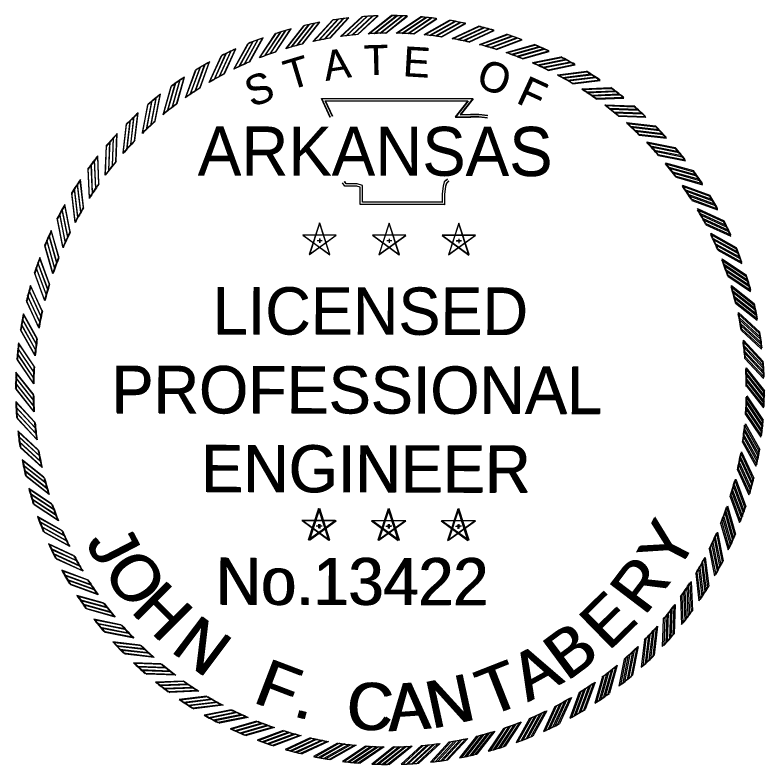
# Model space of a CAD drawing. Extents: x 982240 to 1103002, y 974866 to 1054902.
# Drawn here: x 1095709 to 1103002, y 976312 to 983600 of the extents above; entities that cross this region are included whole.
import ezdxf

# ---------------------------------------------------------------- set-up
doc = ezdxf.new("R2010")
doc.units = 0
doc.layers.add('Default', color=7, linetype='Continuous')

# ---------------------------------------------------------------- blocks, each defined once
blk = doc.blocks.new('STAR')
at = {"layer": 'Default'}
for p, q in [((-0.0001, 0.0615), (-0.0366, -0.0504)), ((0.0362, -0.0503), (0, 0.0617)), ((0.0587, 0.0188), (-0.059, 0.0189)), ((-0.0589, 0.0188), (0.0363, -0.0505)), ((-0.0365, -0.0503), (0.0589, 0.0188)), ((-0.0085, 0), (0.009, 0)), ((0, 0.0063), (0, -0.0085))]:
    blk.add_line(p, q, dxfattribs=at)
blk = doc.blocks.new('RP')
at = {"layer": 'Default'}
for p, q in [((-0.0781, 1.2656), (0.003, 1.33)), ((-0.058, 1.2667), (0.0216, 1.3299)), ((-0.0375, 1.2674), (0.0405, 1.3294)), ((-0.0176, 1.2679), (0.059, 1.3287))]:
    blk.add_line(p, q, dxfattribs=at)
for radius, start, end in [(1.33, 87.4562, 89.8699), (1.268, 90.7933, 93.5307)]:
    blk.add_arc((0, 0), radius, start, end, dxfattribs=at)

msp = doc.modelspace()

# ---------------------------------------------------------------- linework, layer by layer
at = {"layer": 'Default'}
for points in [[(1098774.1, 982603.7), (1098689, 982787.9), (1100160.3, 982788.7), (1100037.4, 982634.3), (1100137.3, 982635.6), (1100220.8, 982636.7), (1100304.2, 982627.6)], [(1098777, 982604.7), (1098692.6, 982789.1), (1100163.8, 982785), (1100040.3, 982630.9), (1100140.3, 982631.9), (1100223.8, 982632.7), (1100307.2, 982623.3)], [(1098795.2, 982613.5), (1098725.5, 982764.6), (1100111.9, 982765.4), (1099988.5, 982610.3), (1100137.6, 982612.3), (1100219.7, 982613.3), (1100301.7, 982604.4)], [(1098798.1, 982614.4), (1098728.9, 982765.7), (1100115.4, 982761.8), (1099991.4, 982607.2), (1100140.5, 982608.6), (1100222.6, 982609.4), (1100304.6, 982600.2)], [(1099928.4, 981987.2), (1099903.3, 981966.8), (1099895, 981936.2), (1099886.7, 981860), (1099886.7, 981758.3), (1099065.4, 981758.3), (1099065.4, 981895.6), (1099065.4, 981926.1), (1099032.1, 981936.2), (1098915.3, 981936.2), (1098894.5, 981967.9)], [(1099929.2, 981984.2), (1099904.1, 981963.9), (1099895.6, 981933.4), (1099887, 981857.2), (1099886.7, 981755.5), (1099065.4, 981758.3), (1099065.9, 981895.6), (1099066, 981926.1), (1099032.7, 981936.4), (1098915.9, 981936.8), (1098895.2, 981968.5)], [(1099913.7, 982005.3), (1099882.8, 981980.1), (1099872.1, 981940.6), (1099863.4, 981861.2), (1099863.4, 981781.6), (1099088.7, 981781.6), (1099088.7, 981895.6), (1099088.7, 981943.3), (1099035.6, 981959.5), (1098927.9, 981959.5), (1098914, 981980.7)], [(1099914.6, 982002.4), (1099883.6, 981977.3), (1099872.7, 981937.8), (1099863.7, 981858.5), (1099863.5, 981778.9), (1099088.8, 981781.5), (1099089.2, 981895.5), (1099089.3, 981943.2), (1099036.3, 981959.6), (1098928.5, 981960), (1098914.8, 981981.2)]]:
    msp.add_lwpolyline(points, dxfattribs=at)

# ---------------------------------------------------------------- block references
for name, p, xscale, yscale, rotation in [('RP', (1099358.4, 979956.4), 2735.2966029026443, 2735.2966029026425, 9.000000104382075), ('RP', (1099352.3, 979955.4), 2735.296602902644, 2735.2966029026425, 8.804199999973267), ('RP', (1099358.4, 979956.4), 2735.2966029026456, 2735.2966029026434, 4.500000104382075), ('RP', (1099352.3, 979955.4), 2735.296602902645, 2735.2966029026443, 4.304199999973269), ('RP', (1099358.4, 979956.4), 2735.2966029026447, 2735.296602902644, 1.0438208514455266e-07), ('RP', (1099352.3, 979955.4), 2735.2966029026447, 2735.296602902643, -0.19580000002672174), ('RP', (1099358.4, 979956.4), 2735.296602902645, 2735.296602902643, -4.499999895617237), ('RP', (1099352.3, 979955.4), 2735.2966029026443, 2735.2966029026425, -4.695800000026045), ('RP', (1099358.4, 979956.4), 2735.296602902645, 2735.2966029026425, -8.999999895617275), ('RP', (1099352.3, 979955.4), 2735.2966029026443, 2735.296602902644, -9.195800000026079), ('RP', (1099358.4, 979956.4), 2735.2966029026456, 2735.2966029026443, -13.499999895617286), ('RP', (1099358.4, 979956.4), 2735.296602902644, 2735.296602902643, 13.500000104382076), ('RP', (1099352.3, 979955.4), 2735.296602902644, 2735.296602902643, 13.304199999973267), ('RP', (1099352.3, 979955.4), 2735.296602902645, 2735.2966029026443, -13.695800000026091), ('RP', (1099358.4, 979956.4), 2735.296602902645, 2735.2966029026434, -17.999999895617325), ('RP', (1099352.3, 979955.4), 2735.296602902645, 2735.296602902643, -18.195800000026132), ('RP', (1099358.4, 979956.4), 2735.2966029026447, 2735.2966029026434, 18.00000010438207), ('RP', (1099352.3, 979955.4), 2735.2966029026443, 2735.2966029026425, 17.80419999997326), ('RP', (1099358.4, 979956.4), 2735.2966029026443, 2735.296602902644, -22.499999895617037), ('RP', (1099358.4, 979956.4), 2735.2966029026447, 2735.2966029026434, 22.50000010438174), ('RP', (1099352.3, 979955.4), 2735.2966029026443, 2735.2966029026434, 22.304199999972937), ('RP', (1099352.3, 979955.4), 2735.2966029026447, 2735.2966029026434, -22.69580000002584), ('RP', (1099358.4, 979956.4), 2735.2966029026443, 2735.2966029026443, 27.000000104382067), ('RP', (1099352.3, 979955.4), 2735.2966029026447, 2735.2966029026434, 26.80419999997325), ('RP', (1099358.4, 979956.4), 2735.2966029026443, 2735.2966029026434, -26.99999989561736), ('RP', (1099352.3, 979955.4), 2735.2966029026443, 2735.296602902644, -27.195800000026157), ('RP', (1099358.4, 979956.4), 2735.296602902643, 2735.2966029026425, 31.50000010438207), ('RP', (1099352.3, 979955.4), 2735.296602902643, 2735.2966029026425, 31.30419999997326), ('RP', (1099358.4, 979956.4), 2735.2966029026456, 2735.2966029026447, -31.499999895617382), ('RP', (1099352.3, 979955.4), 2735.2966029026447, 2735.2966029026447, -31.695800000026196), ('RP', (1099358.4, 979956.4), 2735.296602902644, 2735.296602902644, 36.00000010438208), ('RP', (1099352.3, 979955.4), 2735.2966029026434, 2735.2966029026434, 35.804199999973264), ('RP', (1099358.4, 979956.4), 2735.296602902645, 2735.2966029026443, -35.99999989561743), ('RP', (1099352.3, 979955.4), 2735.2966029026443, 2735.2966029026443, -36.195800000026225), ('RP', (1099358.4, 979956.4), 2735.296602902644, 2735.2966029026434, 40.50000010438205), ('RP', (1099352.3, 979955.4), 2735.296602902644, 2735.296602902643, 40.30419999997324), ('RP', (1099358.4, 979956.4), 2735.296602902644, 2735.2966029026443, -40.49999989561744), ('RP', (1099352.3, 979955.4), 2735.2966029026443, 2735.2966029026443, -40.69580000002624), ('RP', (1099358.4, 979956.4), 2735.296602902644, 2735.2966029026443, -44.99999989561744), ('RP', (1099352.3, 979955.4), 2735.2966029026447, 2735.296602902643, -45.19580000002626), ('RP', (1099358.4, 979956.4), 2735.296602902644, 2735.296602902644, 45.00000010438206), ('RP', (1099352.3, 979955.4), 2735.2966029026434, 2735.2966029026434, 44.80419999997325), ('RP', (1099352.3, 979955.4), 2735.2966029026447, 2735.2966029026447, 49.30419999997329), ('RP', (1099358.4, 979956.4), 2735.296602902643, 2735.296602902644, -49.499999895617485), ('RP', (1099352.3, 979955.4), 2735.296602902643, 2735.2966029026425, -49.69580000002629), ('RP', (1099358.4, 979956.4), 2735.2966029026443, 2735.2966029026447, 49.500000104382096), ('RP', (1099352.3, 979955.4), 2735.296602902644, 2735.296602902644, 53.80419999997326), ('RP', (1099358.4, 979956.4), 2735.296602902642, 2735.2966029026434, -53.9999998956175), ('RP', (1099352.3, 979955.4), 2735.2966029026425, 2735.296602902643, -54.1958000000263), ('RP', (1099358.4, 979956.4), 2735.2966029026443, 2735.296602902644, 54.00000010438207), ('RP', (1099358.4, 979956.4), 2735.2966029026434, 2735.2966029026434, -58.49999989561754), ('RP', (1099352.3, 979955.4), 2735.296602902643, 2735.2966029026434, -58.695800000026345), ('RP', (1099352.3, 979955.4), 2735.296602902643, 2735.2966029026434, 58.30419999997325), ('RP', (1099358.4, 979956.4), 2735.296602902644, 2735.296602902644, 58.50000010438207), ('RP', (1099358.4, 979956.4), 2735.2966029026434, 2735.2966029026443, -62.99999989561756), ('RP', (1099352.3, 979955.4), 2735.296602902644, 2735.2966029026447, 62.80419999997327), ('RP', (1099358.4, 979956.4), 2735.2966029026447, 2735.2966029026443, 63.000000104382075), ('RP', (1099352.3, 979955.4), 2735.2966029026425, 2735.2966029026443, -63.19580000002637), ('STAR', (1098670.4, 981410.2), 2735.2966029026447, 2735.296602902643, -0.19580000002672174), ('STAR', (1098671.6, 981408.9), 2735.2966029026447, 2735.296602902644, 1.0438208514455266e-07), ('STAR', (1099347.1, 981407.9), 2735.2966029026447, 2735.296602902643, -0.19580000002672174), ('STAR', (1099348.3, 981408.9), 2735.2966029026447, 2735.296602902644, 1.0438208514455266e-07), ('STAR', (1100023.7, 981405.6), 2735.2966029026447, 2735.296602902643, -0.19580000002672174), ('STAR', (1100024.9, 981408.9), 2735.2966029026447, 2735.296602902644, 1.0438208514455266e-07), ('RP', (1099352.3, 979955.4), 2735.296602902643, 2735.2966029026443, 67.30419999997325), ('RP', (1099352.3, 979955.4), 2735.296602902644, 2735.296602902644, -67.69580000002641), ('RP', (1099358.4, 979956.4), 2735.296602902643, 2735.296602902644, -67.49999989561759), ('RP', (1099358.4, 979956.4), 2735.296602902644, 2735.296602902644, 67.50000010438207), ('RP', (1099358.4, 979956.4), 2735.2966029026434, 2735.2966029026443, -71.99999989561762), ('RP', (1099352.3, 979955.4), 2735.296602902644, 2735.2966029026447, 71.80419999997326), ('RP', (1099358.4, 979956.4), 2735.2966029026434, 2735.2966029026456, 72.00000010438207), ('RP', (1099352.3, 979955.4), 2735.2966029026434, 2735.2966029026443, -72.19580000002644), ('RP', (1099352.3, 979955.4), 2735.296602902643, 2735.2966029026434, -76.69580000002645), ('RP', (1099358.4, 979956.4), 2735.296602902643, 2735.2966029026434, -76.49999989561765), ('RP', (1099352.3, 979955.4), 2735.2966029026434, 2735.296602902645, 76.30419999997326), ('RP', (1099358.4, 979956.4), 2735.2966029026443, 2735.2966029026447, 76.50000010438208), ('RP', (1099352.3, 979955.4), 2735.2966029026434, 2735.2966029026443, -81.19580000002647), ('RP', (1099358.4, 979956.4), 2735.296602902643, 2735.2966029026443, -80.99999989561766), ('RP', (1099352.3, 979955.4), 2735.2966029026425, 2735.2966029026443, 80.80419999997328), ('RP', (1099358.4, 979956.4), 2735.296602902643, 2735.2966029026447, 81.0000001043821), ('RP', (1099352.3, 979955.4), 2735.296602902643, 2735.2966029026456, 85.30419999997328), ('RP', (1099352.3, 979955.4), 2735.296602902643, 2735.2966029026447, -85.69580000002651), ('RP', (1099358.4, 979956.4), 2735.296602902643, 2735.2966029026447, -85.49999989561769), ('RP', (1099358.4, 979956.4), 2735.296602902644, 2735.2966029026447, 85.50000010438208), ('RP', (1099352.3, 979955.4), 2735.296602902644, 2735.2966029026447, 89.80419999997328), ('RP', (1099358.4, 979956.4), 2735.296602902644, 2735.296602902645, 90.0000001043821), ('RP', (1099352.3, 979955.4), 2735.296602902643, 2735.2966029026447, -90.19580000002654), ('RP', (1099358.4, 979956.4), 2735.296602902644, 2735.296602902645, -89.99999989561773), ('RP', (1099358.4, 979956.4), 2735.2966029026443, 2735.296602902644, -94.49999989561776), ('RP', (1099352.3, 979955.4), 2735.2966029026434, 2735.296602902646, 94.30419999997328), ('RP', (1099358.4, 979956.4), 2735.296602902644, 2735.2966029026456, 94.5000001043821), ('RP', (1099352.3, 979955.4), 2735.2966029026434, 2735.2966029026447, -94.69580000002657), ('RP', (1099352.3, 979955.4), 2735.296602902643, 2735.2966029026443, -99.19580000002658), ('RP', (1099358.4, 979956.4), 2735.296602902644, 2735.2966029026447, -98.99999989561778), ('RP', (1099352.3, 979955.4), 2735.296602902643, 2735.296602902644, 98.8041999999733), ('RP', (1099358.4, 979956.4), 2735.296602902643, 2735.296602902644, 99.0000001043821), ('RP', (1099352.3, 979955.4), 2735.2966029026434, 2735.2966029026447, 103.30419999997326), ('RP', (1099352.3, 979955.4), 2735.296602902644, 2735.296602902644, -103.69580000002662), ('RP', (1099358.4, 979956.4), 2735.2966029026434, 2735.2966029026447, -103.49999989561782), ('RP', (1099358.4, 979956.4), 2735.2966029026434, 2735.2966029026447, 103.50000010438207), ('RP', (1099352.3, 979955.4), 2735.2966029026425, 2735.296602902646, 107.80419999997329), ('RP', (1099358.4, 979956.4), 2735.2966029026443, 2735.296602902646, 108.0000001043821), ('RP', (1099352.3, 979955.4), 2735.2966029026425, 2735.2966029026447, -108.19580000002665), ('RP', (1099358.4, 979956.4), 2735.296602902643, 2735.296602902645, -107.99999989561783), ('STAR', (1098660.9, 978635.8), 2735.2966029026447, 2735.296602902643, -0.19580000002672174), ('STAR', (1098671.6, 978634.5), 2735.2966029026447, 2735.296602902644, 1.0438208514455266e-07), ('STAR', (1099337.6, 978633.5), 2735.2966029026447, 2735.296602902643, -0.19580000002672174), ('STAR', (1099348.3, 978634.5), 2735.2966029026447, 2735.296602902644, 1.0438208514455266e-07), ('STAR', (1100024.9, 978634.5), 2735.2966029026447, 2735.296602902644, 1.0438208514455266e-07), ('RP', (1099352.3, 979955.4), 2735.296602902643, 2735.296602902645, -112.69580000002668), ('RP', (1099358.4, 979956.4), 2735.296602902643, 2735.296602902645, -112.49999989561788), ('RP', (1099352.3, 979955.4), 2735.2966029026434, 2735.2966029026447, 112.3041999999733), ('RP', (1099358.4, 979956.4), 2735.2966029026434, 2735.2966029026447, 112.5000001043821), ('STAR', (1100014.2, 978631.2), 2735.2966029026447, 2735.296602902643, -0.19580000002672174), ('RP', (1099352.3, 979955.4), 2735.2966029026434, 2735.2966029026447, 116.80419999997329), ('RP', (1099358.4, 979956.4), 2735.2966029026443, 2735.2966029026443, 117.0000001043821), ('RP', (1099352.3, 979955.4), 2735.2966029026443, 2735.296602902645, -117.19580000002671), ('RP', (1099358.4, 979956.4), 2735.2966029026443, 2735.296602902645, -116.9999998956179), ('RP', (1099352.3, 979955.4), 2735.296602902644, 2735.2966029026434, 121.30419999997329), ('RP', (1099352.3, 979955.4), 2735.2966029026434, 2735.2966029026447, -121.69580000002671), ('RP', (1099358.4, 979956.4), 2735.296602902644, 2735.296602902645, -121.4999998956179), ('RP', (1099358.4, 979956.4), 2735.296602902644, 2735.2966029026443, 121.5000001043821), ('RP', (1099352.3, 979955.4), 2735.296602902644, 2735.2966029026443, -126.19580000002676), ('RP', (1099358.4, 979956.4), 2735.2966029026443, 2735.2966029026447, -125.99999989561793), ('RP', (1099352.3, 979955.4), 2735.2966029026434, 2735.296602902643, 125.80419999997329), ('RP', (1099358.4, 979956.4), 2735.2966029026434, 2735.2966029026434, 126.00000010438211), ('RP', (1099352.3, 979955.4), 2735.296602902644, 2735.296602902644, -130.6958000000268), ('RP', (1099358.4, 979956.4), 2735.2966029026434, 2735.2966029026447, -130.49999989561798), ('RP', (1099352.3, 979955.4), 2735.2966029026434, 2735.2966029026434, 130.3041999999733), ('RP', (1099358.4, 979956.4), 2735.2966029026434, 2735.296602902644, 130.50000010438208), ('RP', (1099352.3, 979955.4), 2735.2966029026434, 2735.2966029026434, -135.19580000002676), ('RP', (1099358.4, 979956.4), 2735.296602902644, 2735.296602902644, -134.99999989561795), ('RP', (1099352.3, 979955.4), 2735.296602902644, 2735.296602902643, 134.8041999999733), ('RP', (1099358.4, 979956.4), 2735.296602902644, 2735.296602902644, 135.0000001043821), ('RP', (1099352.3, 979955.4), 2735.296602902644, 2735.296602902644, 139.30419999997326), ('RP', (1099358.4, 979956.4), 2735.2966029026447, 2735.2966029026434, 139.50000010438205), ('RP', (1099352.3, 979955.4), 2735.296602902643, 2735.2966029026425, -139.69580000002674), ('RP', (1099358.4, 979956.4), 2735.2966029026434, 2735.296602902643, -139.49999989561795), ('RP', (1099352.3, 979955.4), 2735.296602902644, 2735.296602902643, -144.19580000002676), ('RP', (1099358.4, 979956.4), 2735.296602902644, 2735.296602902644, -143.99999989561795), ('RP', (1099352.3, 979955.4), 2735.296602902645, 2735.296602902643, 143.8041999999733), ('RP', (1099358.4, 979956.4), 2735.2966029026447, 2735.2966029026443, 144.00000010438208), ('RP', (1099352.3, 979955.4), 2735.296602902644, 2735.2966029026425, 148.3041999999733), ('RP', (1099358.4, 979956.4), 2735.296602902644, 2735.296602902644, 148.50000010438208), ('RP', (1099352.3, 979955.4), 2735.296602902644, 2735.2966029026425, -148.69580000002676), ('RP', (1099358.4, 979956.4), 2735.296602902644, 2735.2966029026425, -148.49999989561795), ('RP', (1099352.3, 979955.4), 2735.296602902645, 2735.2966029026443, 152.8041999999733), ('RP', (1099358.4, 979956.4), 2735.296602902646, 2735.2966029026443, 153.00000010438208), ('RP', (1099352.3, 979955.4), 2735.296602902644, 2735.2966029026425, -153.1958000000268), ('RP', (1099358.4, 979956.4), 2735.296602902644, 2735.2966029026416, -152.99999989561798), ('RP', (1099352.3, 979955.4), 2735.2966029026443, 2735.2966029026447, -157.6958000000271), ('RP', (1099358.4, 979956.4), 2735.2966029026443, 2735.2966029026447, -157.4999998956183), ('RP', (1099352.3, 979955.4), 2735.2966029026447, 2735.2966029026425, 157.3041999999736), ('RP', (1099358.4, 979956.4), 2735.2966029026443, 2735.296602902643, 157.50000010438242), ('RP', (1099352.3, 979955.4), 2735.296602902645, 2735.296602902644, 161.8041999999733), ('RP', (1099358.4, 979956.4), 2735.2966029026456, 2735.296602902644, 162.00000010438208), ('RP', (1099352.3, 979955.4), 2735.2966029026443, 2735.2966029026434, -162.19580000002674), ('RP', (1099358.4, 979956.4), 2735.2966029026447, 2735.2966029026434, -161.99999989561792), ('RP', (1099352.3, 979955.4), 2735.296602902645, 2735.296602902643, 166.3041999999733), ('RP', (1099358.4, 979956.4), 2735.296602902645, 2735.296602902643, 166.50000010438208), ('RP', (1099352.3, 979955.4), 2735.296602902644, 2735.296602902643, -166.69580000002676), ('RP', (1099358.4, 979956.4), 2735.296602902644, 2735.296602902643, -166.49999989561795), ('RP', (1099352.3, 979955.4), 2735.2966029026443, 2735.2966029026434, 170.8041999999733), ('RP', (1099358.4, 979956.4), 2735.2966029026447, 2735.2966029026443, 171.00000010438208), ('RP', (1099352.3, 979955.4), 2735.2966029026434, 2735.296602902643, -171.19580000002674), ('RP', (1099358.4, 979956.4), 2735.2966029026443, 2735.2966029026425, -170.99999989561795), ('RP', (1099352.3, 979955.4), 2735.2966029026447, 2735.296602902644, 175.3041999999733), ('RP', (1099358.4, 979956.4), 2735.2966029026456, 2735.296602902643, 175.50000010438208), ('RP', (1099352.3, 979955.4), 2735.2966029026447, 2735.296602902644, 179.8041999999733), ('RP', (1099358.4, 979956.4), 2735.296602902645, 2735.296602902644, -179.99999989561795), ('RP', (1099352.3, 979955.4), 2735.296602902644, 2735.296602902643, -175.69580000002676), ('RP', (1099358.4, 979956.4), 2735.2966029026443, 2735.296602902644, -175.49999989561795)]:
    msp.add_blockref(name, p, dxfattribs=dict(at, xscale=xscale, yscale=yscale, rotation=rotation))

# ---------------------------------------------------------------- texts
for s, height, rotation, p in [('A', 290.2, 8.67877, (1098729.2, 982957.9)), ('A', 290.2, 8.48297, (1098733.3, 982959)), ('T', 290.2, 1.47887, (1099104, 983015.6)), ('T', 290.2, 1.28307, (1099108.3, 983015.5)), ('E', 290.2, 356.67203, (1099475.4, 983006.8)), ('E', 290.2, 356.47623, (1099479.7, 983005.4)), ('T', 290.2, 16.90148, (1098376.8, 982865.9)), ('T', 290.2, 16.70568, (1098380.6, 982868.2)), ('O', 290.2, 341.2218, (1100180.1, 982907.3)), ('O', 290.2, 341.026, (1100184, 982903.5)), ('S', 290.2, 19.77256, (1098007.8, 982700.2)), ('S', 290.2, 19.57676, (1098011, 982703.8)), ('F', 290.2, 335.36282, (1100571.2, 982754.4)), ('F', 290.2, 335.16702, (1100574.6, 982749.2)), ('ARKANSAS', 473.65, 359.8042, (1097487.3, 982045.5)), ('LICENSED', 458.55, 359.8042, (1097629.1, 980498.9)), ('PROFESSIONAL', 458.545, 359.8042, (1096643.9, 979735.4)), ('ENGINEER', 458.55, 359.8042, (1097514.7, 978965.5)), ('Y', 458.5, 62.53917, (1102147.6, 978155.8)), ('Y', 458.5, 62.73497, (1102159.9, 978166.4)), ('J', 458.5, 297.28129, (1096388.3, 978481.6)), ('J', 458.5, 297.47709, (1096399.5, 978472.5)), ('O', 458.5, 304.18986, (1096550.7, 978200.4)), ('O', 458.5, 304.38567, (1096562.9, 978191.8)), ('No.13422', 456.74, 359.8042, (1097655.7, 977872)), ('R', 458.5, 52.74372, (1101827.5, 977752)), ('R', 458.5, 52.93952, (1101841.2, 977761.5)), ('H', 458.5, 314.74471, (1096821.2, 977805.3)), ('H', 458.5, 314.94051, (1096834.7, 977797.7)), ('E', 458.5, 44.50182, (1101493, 977419)), ('E', 458.5, 44.30602, (1101478.2, 977410.7)), ('N', 458.5, 322.9417, (1097208.4, 977422)), ('N', 458.5, 323.1375, (1097223.2, 977415.7)), ('B', 458.5, 36.50499, (1101073.5, 977118.9)), ('B', 458.5, 36.70079, (1101089.3, 977125.8)), ('A', 458.5, 28.85621, (1100692.6, 976918.9)), ('A', 458.5, 29.05201, (1100709.1, 976924.4)), ('F', 458.5, 339.0288, (1098008.8, 976925.4)), ('F', 458.5, 339.2246, (1098025.3, 976921.8)), ('T', 458.5, 21.43291, (1100311.4, 976775.4)), ('T', 458.5, 21.62871, (1100328.4, 976779.7)), ('N', 458.5, 12.07026, (1099758.2, 976661.1)), ('N', 458.5, 12.26606, (1099775.7, 976663.5)), ('C', 458.5, 356.10284, (1098918.5, 976668)), ('C', 458.5, 356.29864, (1098935.9, 976667.5)), ('A', 458.5, 3.90916, (1099339.1, 976637.6)), ('A', 458.5, 4.10496, (1099356.6, 976638.5)), ('.', 458.5, 344.7037, (1098399.9, 976789.8)), ('.', 458.5, 344.8995, (1098416.9, 976787.5))]:
    msp.add_text(s, height=height, rotation=rotation, dxfattribs=at).set_placement(p)
for s, height, p in [('ARKANSAS', 473.65, (1097486.4, 982040.1)), ('LICENSED', 458.55, (1097633.4, 980494)), ('PROFESSIONAL', 458.545, (1096650.8, 979727.1)), ('ENGINEER', 458.55, (1097524.2, 978960.3)), ('No.13422', 456.74, (1097669, 977867.2))]:
    msp.add_text(s, height=height, dxfattribs=at).set_placement(p)

doc.saveas('drawing.dxf')
